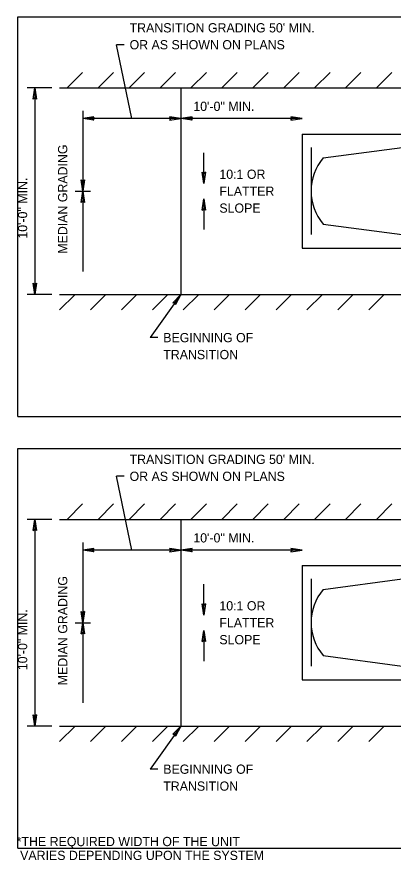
# Model space of a CAD drawing. Extents: x 12.3 to 19.6, y 6 to 16.1.
# Drawn here: x 12.61 to 15.05, y 10.6 to 16.08 of the extents above; entities that cross this region are included whole.
import ezdxf

# ---------------------------------------------------------------- set-up
doc = ezdxf.new("R2010")
doc.units = 0
for name, color, linetype in [('Default', 7, 'Continuous'), ('DETL-DIMS', 7, 'Continuous'), ('DETL-LINE', 7, 'Continuous'), ('DETL-NOTE', 7, 'Continuous')]:
    doc.layers.add(name, color=color, linetype=linetype)

msp = doc.modelspace()

# ---------------------------------------------------------------- linework, layer by layer
at = {"layer": 'Default'}
for p, q in [((12.6137, 13.4842), (12.6137, 16.0809)), ((12.6137, 16.0809), (19.2537, 16.0809)), ((12.6137, 13.4842), (19.2537, 13.4842)), ((12.6137, 10.6809), (12.6137, 13.2777)), ((12.6137, 13.2777), (19.2537, 13.2777)), ((12.6137, 10.6809), (19.2537, 10.6809))]:
    msp.add_line(p, q, dxfattribs=at)
at = {"layer": 'DETL-DIMS'}
for p, q in [((13.3021, 15.8999), (13.2521, 15.8999)), ((13.3521, 15.4199), (13.2521, 15.8999)), ((12.8337, 15.6199), (12.6737, 15.6199)), ((12.7131, 15.547), (12.7237, 15.6199)), ((12.7237, 15.6199), (12.7237, 14.2774)), ((12.7343, 15.547), (12.7237, 15.6199)), ((12.7131, 15.547), (12.7237, 15.5561)), ((12.7343, 15.547), (12.7237, 15.5561)), ((13.0337, 15.4699), (13.0337, 14.4274)), ((13.1066, 15.4305), (13.0337, 15.4199)), ((13.6705, 15.4199), (13.0337, 15.4199)), ((13.1066, 15.4093), (13.0337, 15.4199)), ((13.1066, 15.4305), (13.0975, 15.4199)), ((13.1066, 15.4093), (13.0975, 15.4199)), ((13.5976, 15.4305), (13.6705, 15.4199)), ((13.5976, 15.4305), (13.6067, 15.4199)), ((13.5976, 15.4093), (13.6705, 15.4199)), ((13.5976, 15.4093), (13.6067, 15.4199)), ((13.7434, 15.4305), (13.6705, 15.4199)), ((14.4574, 15.4199), (13.6705, 15.4199)), ((13.7434, 15.4093), (13.6705, 15.4199)), ((13.7434, 15.4305), (13.7343, 15.4199)), ((13.7434, 15.4093), (13.7343, 15.4199)), ((14.3845, 15.4305), (14.4574, 15.4199)), ((14.3845, 15.4305), (14.3936, 15.4199)), ((14.3845, 15.4093), (14.4574, 15.4199)), ((14.3845, 15.4093), (14.3936, 15.4199)), ((13.8205, 14.9987), (13.8205, 15.1987)), ((13.8099, 15.0716), (13.8205, 14.9987)), ((13.8099, 15.0716), (13.8205, 15.0625)), ((13.8311, 15.0716), (13.8205, 14.9987)), ((13.8311, 15.0716), (13.8205, 15.0625)), ((13.0231, 15.0216), (13.0337, 14.9487)), ((13.0231, 15.0216), (13.0337, 15.0125)), ((13.0443, 15.0216), (13.0337, 14.9487)), ((13.0443, 15.0216), (13.0337, 15.0125)), ((12.9837, 14.9487), (13.0837, 14.9487)), ((13.0231, 14.8758), (13.0337, 14.9487)), ((13.0443, 14.8758), (13.0337, 14.9487)), ((13.0231, 14.8758), (13.0337, 14.8849)), ((13.0443, 14.8758), (13.0337, 14.8849)), ((13.8099, 14.8258), (13.8205, 14.8987)), ((13.8311, 14.8258), (13.8205, 14.8987)), ((13.8205, 14.8987), (13.8205, 14.6987)), ((13.8099, 14.8258), (13.8205, 14.8349)), ((13.8311, 14.8258), (13.8205, 14.8349)), ((12.7131, 14.3503), (12.7237, 14.2774)), ((12.7131, 14.3503), (12.7237, 14.3412)), ((12.7343, 14.3503), (12.7237, 14.2774)), ((12.7343, 14.3503), (12.7237, 14.3412)), ((12.8337, 14.2774), (12.6737, 14.2774)), ((13.6705, 14.2774), (13.4705, 13.9974)), ((13.6195, 14.2243), (13.6705, 14.2774)), ((13.6368, 14.212), (13.6705, 14.2774)), ((13.6195, 14.2243), (13.6335, 14.2255)), ((13.6368, 14.212), (13.6335, 14.2255)), ((13.5205, 13.9974), (13.4705, 13.9974)), ((13.3021, 13.0967), (13.2521, 13.0967)), ((13.3521, 12.6167), (13.2521, 13.0967)), ((12.8337, 12.8167), (12.6737, 12.8167)), ((12.7131, 12.7438), (12.7237, 12.8167)), ((12.7237, 12.8167), (12.7237, 11.4742)), ((12.7343, 12.7438), (12.7237, 12.8167)), ((12.7131, 12.7438), (12.7237, 12.7529)), ((12.7343, 12.7438), (12.7237, 12.7529)), ((13.0337, 12.6667), (13.0337, 11.6242)), ((13.1066, 12.6273), (13.0337, 12.6167)), ((13.6705, 12.6167), (13.0337, 12.6167)), ((13.1066, 12.6061), (13.0337, 12.6167)), ((13.1066, 12.6273), (13.0975, 12.6167)), ((13.1066, 12.6061), (13.0975, 12.6167)), ((13.5976, 12.6273), (13.6705, 12.6167)), ((13.5976, 12.6273), (13.6067, 12.6167)), ((13.5976, 12.6061), (13.6705, 12.6167)), ((13.5976, 12.6061), (13.6067, 12.6167)), ((13.7434, 12.6273), (13.6705, 12.6167)), ((14.4574, 12.6167), (13.6705, 12.6167)), ((13.7434, 12.6061), (13.6705, 12.6167)), ((13.7434, 12.6273), (13.7343, 12.6167)), ((13.7434, 12.6061), (13.7343, 12.6167)), ((14.3845, 12.6273), (14.4574, 12.6167)), ((14.3845, 12.6273), (14.3936, 12.6167)), ((14.3845, 12.6061), (14.4574, 12.6167)), ((14.3845, 12.6061), (14.3936, 12.6167)), ((13.8205, 12.1954), (13.8205, 12.3954)), ((13.0231, 12.2183), (13.0337, 12.1454)), ((13.0231, 12.2183), (13.0337, 12.2092)), ((13.0443, 12.2183), (13.0337, 12.1454)), ((13.0443, 12.2183), (13.0337, 12.2092)), ((13.8099, 12.2683), (13.8205, 12.1954)), ((13.8099, 12.2683), (13.8205, 12.2592)), ((13.8311, 12.2683), (13.8205, 12.1954)), ((13.8311, 12.2683), (13.8205, 12.2592)), ((12.9837, 12.1454), (13.0837, 12.1454)), ((13.0231, 12.0725), (13.0337, 12.1454)), ((13.0443, 12.0725), (13.0337, 12.1454)), ((13.0231, 12.0725), (13.0337, 12.0816)), ((13.0443, 12.0725), (13.0337, 12.0816)), ((13.8099, 12.0225), (13.8205, 12.0954)), ((13.8311, 12.0225), (13.8205, 12.0954)), ((13.8205, 12.0954), (13.8205, 11.8954)), ((13.8099, 12.0225), (13.8205, 12.0316)), ((13.8311, 12.0225), (13.8205, 12.0316)), ((12.7131, 11.5471), (12.7237, 11.4742)), ((12.7131, 11.5471), (12.7237, 11.538)), ((12.7343, 11.5471), (12.7237, 11.4742)), ((12.7343, 11.5471), (12.7237, 11.538)), ((12.8337, 11.4742), (12.6737, 11.4742)), ((13.6705, 11.4742), (13.4705, 11.1942)), ((13.6195, 11.421), (13.6705, 11.4742)), ((13.6368, 11.4087), (13.6705, 11.4742)), ((13.6195, 11.421), (13.6335, 11.4222)), ((13.6368, 11.4087), (13.6335, 11.4222)), ((13.5205, 11.1942), (13.4705, 11.1942))]:
    msp.add_line(p, q, dxfattribs=at)
for points in [[(12.7131, 15.547), (12.7237, 15.6199), (12.7343, 15.547), (12.7237, 15.5561)], [(13.1066, 15.4093), (13.0337, 15.4199), (13.1066, 15.4305), (13.0975, 15.4199)], [(13.5976, 15.4093), (13.6705, 15.4199), (13.5976, 15.4305), (13.6067, 15.4199)], [(13.7434, 15.4093), (13.6705, 15.4199), (13.7434, 15.4305), (13.7343, 15.4199)], [(14.3845, 15.4093), (14.4574, 15.4199), (14.3845, 15.4305), (14.3936, 15.4199)], [(13.8311, 15.0716), (13.8205, 14.9987), (13.8099, 15.0716), (13.8205, 15.0625)], [(13.0443, 15.0216), (13.0337, 14.9487), (13.0231, 15.0216), (13.0337, 15.0125)], [(13.0231, 14.8758), (13.0337, 14.9487), (13.0443, 14.8758), (13.0337, 14.8849)], [(13.8099, 14.8258), (13.8205, 14.8987), (13.8311, 14.8258), (13.8205, 14.8349)], [(12.7343, 14.3503), (12.7237, 14.2774), (12.7131, 14.3503), (12.7237, 14.3412)], [(13.6195, 14.2243), (13.6705, 14.2774), (13.6368, 14.212), (13.6335, 14.2255)], [(12.7131, 12.7438), (12.7237, 12.8167), (12.7343, 12.7438), (12.7237, 12.7529)], [(13.1066, 12.6061), (13.0337, 12.6167), (13.1066, 12.6273), (13.0975, 12.6167)], [(13.5976, 12.6061), (13.6705, 12.6167), (13.5976, 12.6273), (13.6067, 12.6167)], [(13.7434, 12.6061), (13.6705, 12.6167), (13.7434, 12.6273), (13.7343, 12.6167)], [(14.3845, 12.6061), (14.4574, 12.6167), (14.3845, 12.6273), (14.3936, 12.6167)], [(13.0443, 12.2183), (13.0337, 12.1454), (13.0231, 12.2183), (13.0337, 12.2092)], [(13.8311, 12.2683), (13.8205, 12.1954), (13.8099, 12.2683), (13.8205, 12.2592)], [(13.0231, 12.0725), (13.0337, 12.1454), (13.0443, 12.0725), (13.0337, 12.0816)], [(13.8099, 12.0225), (13.8205, 12.0954), (13.8311, 12.0225), (13.8205, 12.0316)], [(12.7343, 11.5471), (12.7237, 11.4742), (12.7131, 11.5471), (12.7237, 11.538)], [(13.6195, 11.421), (13.6705, 11.4742), (13.6368, 11.4087), (13.6335, 11.4222)]]:
    msp.add_lwpolyline(points, close=True, dxfattribs=at)
at = {"layer": 'DETL-LINE'}
for p, q in [((12.9333, 15.6199), (13.0333, 15.7199)), ((13.134, 15.6199), (13.234, 15.7199)), ((13.3347, 15.6199), (13.4347, 15.7199)), ((13.5353, 15.6199), (13.6353, 15.7199)), ((13.736, 15.6199), (13.836, 15.7199)), ((13.9366, 15.6199), (14.0366, 15.7199)), ((14.1373, 15.6199), (14.2373, 15.7199)), ((14.3379, 15.6199), (14.4379, 15.7199)), ((14.5386, 15.6199), (14.6386, 15.7199)), ((14.7393, 15.6199), (14.8393, 15.7199)), ((14.9399, 15.6199), (15.0399, 15.7199)), ((12.8837, 15.6199), (19.2537, 15.6199)), ((13.6705, 15.6199), (13.6705, 14.2774)), ((14.4574, 15.3199), (14.4574, 14.5774)), ((14.4574, 15.3199), (18.7293, 15.3199)), ((14.5159, 15.2331), (14.5159, 14.6669)), ((14.5945, 15.1649), (15.106, 15.2331)), ((14.5945, 14.7351), (15.106, 14.6669)), ((14.4574, 14.5774), (18.7293, 14.5774)), ((12.8837, 14.2774), (19.2537, 14.2774)), ((12.8837, 14.1774), (12.9837, 14.2774)), ((13.0844, 14.1774), (13.1844, 14.2774)), ((13.285, 14.1774), (13.385, 14.2774)), ((13.4857, 14.1774), (13.5857, 14.2774)), ((13.6863, 14.1774), (13.7863, 14.2774)), ((13.887, 14.1774), (13.987, 14.2774)), ((14.0876, 14.1774), (14.1876, 14.2774)), ((14.2883, 14.1774), (14.3883, 14.2774)), ((14.489, 14.1774), (14.589, 14.2774)), ((14.6896, 14.1774), (14.7896, 14.2774)), ((14.8903, 14.1774), (14.9903, 14.2774)), ((12.9333, 12.8167), (13.0333, 12.9167)), ((13.134, 12.8167), (13.234, 12.9167)), ((13.3347, 12.8167), (13.4347, 12.9167)), ((13.5353, 12.8167), (13.6353, 12.9167)), ((13.736, 12.8167), (13.836, 12.9167)), ((13.9366, 12.8167), (14.0366, 12.9167)), ((14.1373, 12.8167), (14.2373, 12.9167)), ((14.3379, 12.8167), (14.4379, 12.9167)), ((14.5386, 12.8167), (14.6386, 12.9167)), ((14.7393, 12.8167), (14.8393, 12.9167)), ((14.9399, 12.8167), (15.0399, 12.9167)), ((12.8837, 12.8167), (19.2537, 12.8167)), ((13.6705, 12.8167), (13.6705, 11.4742)), ((14.4574, 12.5167), (14.4574, 11.7742)), ((14.4574, 12.5167), (18.7293, 12.5167)), ((14.5159, 12.4298), (14.5159, 11.8636)), ((14.5945, 12.3616), (15.106, 12.4298)), ((14.5945, 11.9318), (15.106, 11.8636)), ((14.4574, 11.7742), (18.7293, 11.7742)), ((12.8837, 11.4742), (19.2537, 11.4742)), ((12.8837, 11.3742), (12.9837, 11.4742)), ((13.0844, 11.3742), (13.1844, 11.4742)), ((13.285, 11.3742), (13.385, 11.4742)), ((13.4857, 11.3742), (13.5857, 11.4742)), ((13.6863, 11.3742), (13.7863, 11.4742)), ((13.887, 11.3742), (13.987, 11.4742)), ((14.0876, 11.3742), (14.1876, 11.4742)), ((14.2883, 11.3742), (14.3883, 11.4742)), ((14.489, 11.3742), (14.589, 11.4742)), ((14.6896, 11.3742), (14.7896, 11.4742)), ((14.8903, 11.3742), (14.9903, 11.4742))]:
    msp.add_line(p, q, dxfattribs=at)
for centre in [(14.8486, 14.95), (14.8486, 12.1467)]:
    msp.add_arc(centre, 0.3327, 139.7757, 220.2243, dxfattribs=at)

# ---------------------------------------------------------------- texts
at = {"layer": 'DETL-NOTE'}
for s, rotation, p in [("TRANSITION GRADING 50' MIN.", 360, (13.3379, 15.9799)), ('OR AS SHOWN ON PLANS', 360, (13.3379, 15.8699)), ('10\'-0" MIN.', 360, (13.7515, 15.4699)), ('MEDIAN GRADING', 90, (12.9337, 14.5429)), ('10:1 OR', 360, (13.9205, 15.0287)), ('10\'-0" MIN.', 90, (12.6737, 14.6404)), ('FLATTER', 360, (13.9205, 14.9187)), ('SLOPE', 360, (13.9205, 14.8087)), ('BEGINNING OF', 360, (13.5563, 13.9674)), ('TRANSITION', 360, (13.5563, 13.8574)), ("TRANSITION GRADING 50' MIN.", 360, (13.3379, 13.1767)), ('OR AS SHOWN ON PLANS', 360, (13.3379, 13.0667)), ('10\'-0" MIN.', 360, (13.7515, 12.6667)), ('MEDIAN GRADING', 90, (12.9337, 11.7396)), ('10:1 OR', 360, (13.9205, 12.2254)), ('10\'-0" MIN.', 90, (12.6737, 11.8371)), ('FLATTER', 360, (13.9205, 12.1154)), ('SLOPE', 360, (13.9205, 12.0054)), ('BEGINNING OF', 360, (13.5563, 11.1642)), ('TRANSITION', 360, (13.5563, 11.0542))]:
    msp.add_text(s, height=0.06, rotation=rotation, dxfattribs=at).set_placement(p)
for s, p in [('*THE REQUIRED WIDTH OF THE UNIT', (12.6053, 10.6942)), (' VARIES DEPENDING UPON THE SYSTEM', (12.6053, 10.6042))]:
    msp.add_text(s, height=0.06, dxfattribs=at).set_placement(p)

doc.saveas('drawing.dxf')
